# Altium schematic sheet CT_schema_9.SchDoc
size 274 x 160 mm
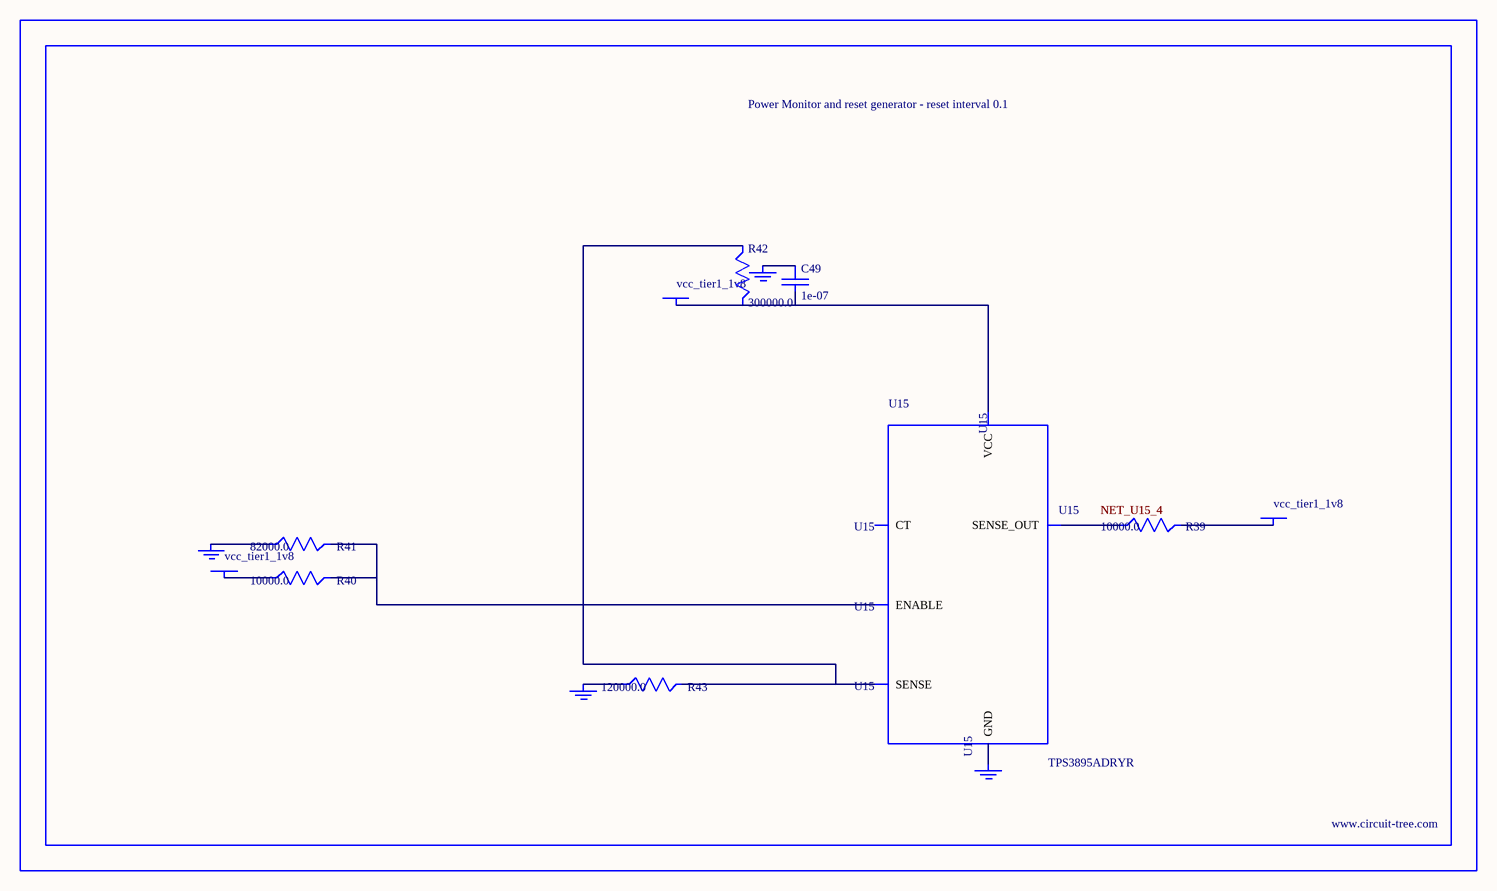
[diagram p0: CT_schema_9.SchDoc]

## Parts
BORDER8  (no value)
C49  1e-07  [C0402]
GND_INSTANCE_8_0  (no value)
GND_INSTANCE_8_1  (no value)
GND_INSTANCE_8_2  (no value)
GND_INSTANCE_8_3  (no value)
POWER_INSTANCE_8_0  vcc_tier1_1v8
POWER_INSTANCE_8_1  vcc_tier1_1v8
POWER_INSTANCE_8_2  vcc_tier1_1v8
R39  10000.0  [R0603]
R40  10000.0  [R0603]
R41  82000.0  [R0603]
R42  300000.0  [R0603]
R43  120000.0  [R0603]
U15  TPS3895ADRYR  [SON-6]

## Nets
NetC49_1: C49.1 GND_INSTANCE_8_2.0(GND)
NetC49_2: C49.2 POWER_INSTANCE_8_2.0(PWR) R42.2 U15.6(VCC)
NetGND_INSTANCE_8_0_0: GND_INSTANCE_8_0.0(GND) R41.1
NetGND_INSTANCE_8_1_0: GND_INSTANCE_8_1.0(GND) R43.1
NetGND_INSTANCE_8_3_0: GND_INSTANCE_8_3.0(GND) U15.2(GND)
NetPOWER_INSTANCE_8_0_0: POWER_INSTANCE_8_0.0(PWR) R40.1
NetPOWER_INSTANCE_8_1_0: POWER_INSTANCE_8_1.0(PWR) R39.2
NetR39_1: R39.1 U15.4(SENSE_OUT)
NetR40_2: R40.2 R41.2 U15.1(ENABLE)
NetR42_1: R42.1 R43.2 U15.3(SENSE)

Not connected (* = marked no-connect by the designer): U15 5(CT)

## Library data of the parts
BORDER8 = BORDER_PAGE8
C49 = C0402C104K3RACTU
GND_INSTANCE_8_0-GND_INSTANCE_8_3 = GND
POWER_INSTANCE_8_0-POWER_INSTANCE_8_2 = PWR
R39 R40 = RC0603JR-0710KL
R41 = RC0603JR-0782KL
R42 = RC0603JR-07300KL
R43 = RC0603JR-07120KL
